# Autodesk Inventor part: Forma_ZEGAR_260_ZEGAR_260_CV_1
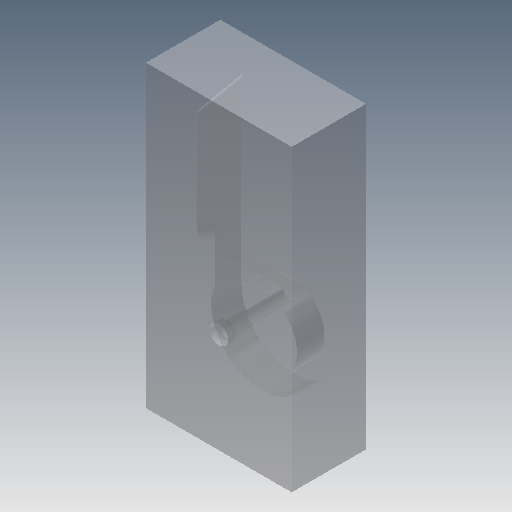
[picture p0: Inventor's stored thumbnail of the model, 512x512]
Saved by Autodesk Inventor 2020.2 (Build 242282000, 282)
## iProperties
Created: 2015-01
Part Number: Forma_ZEGAR_260_ZEGAR_260_CV_1
Material: Ogólny
Document SubType Name: Modeling
Designer: F.Stasiak
Density: 1 g/cm^3
Appearance: Domyślna
Catalog Web Link: www.expertbooks.pl
Manager: www.cadconsulting.pl
Company: Fabian Stasiak CAD Consulting
Author: F.Stasiak
Subject: Zbiór ćwiczeń. Autodesk Inventor 2020. Kurs Professional
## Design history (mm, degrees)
node "Forma_ZEGAR_260_ZEGAR_260_CV_Base"
feature "Bryła5::Forma_ZEGAR_260_ZEGAR_260_CV_Base"
tag "Bryła wyprowadzona5"
node "Bryła5"
feature "Forma_ZEGAR_260_ZEGAR_260_CV_Base_Bodies"
other parameters: "d24" = 0, "d25" = -26.4075, "d27" = 0, "d28" = -180 deg, "d29" = 0
